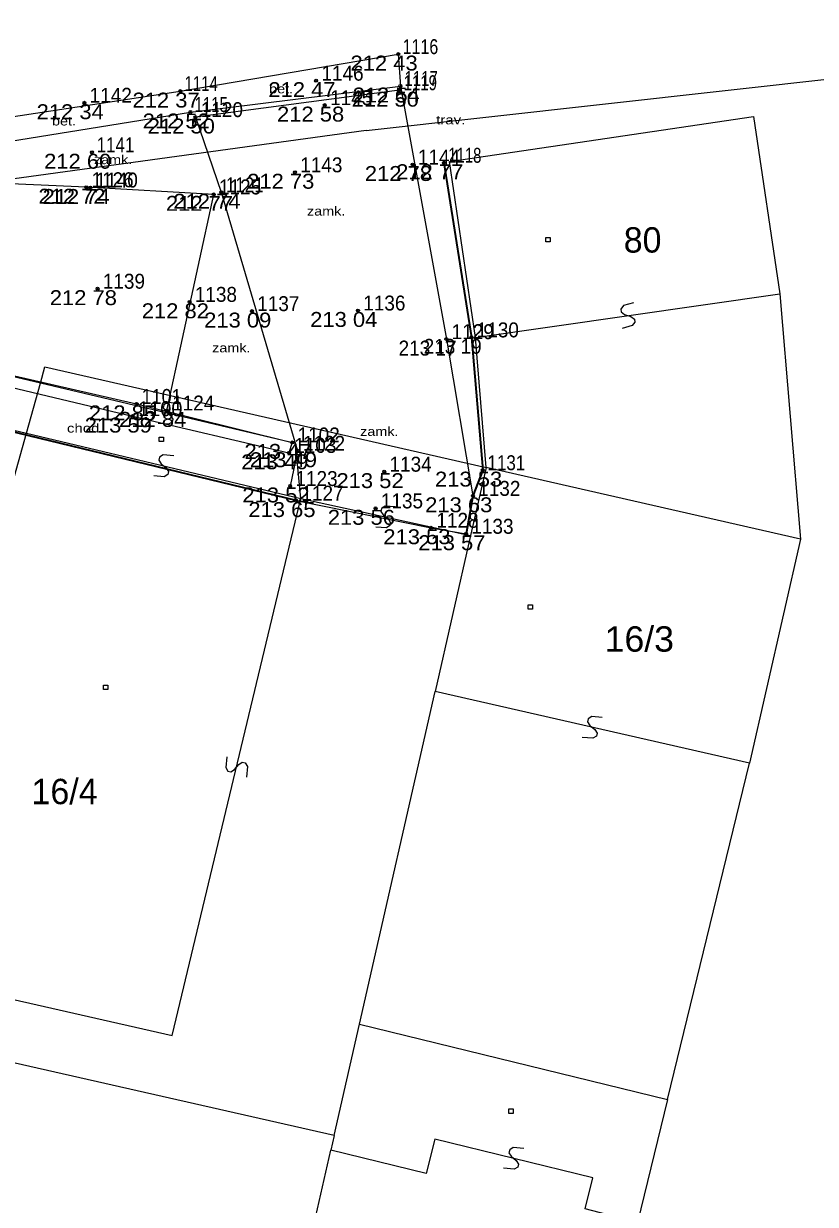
# Model space of a CAD drawing. Extents: x -736847 to -736508, y -1028413 to -1028271.
# Drawn here: x -736628.79 to -736602.28, y -1028331.58 to -1028292.02 of the extents above; entities that cross this region are included whole.
import ezdxf
from ezdxf.enums import TextEntityAlignment as Align

# ---------------------------------------------------------------- set-up
doc = ezdxf.new("R2010")
doc.units = 0
doc.header["$LTSCALE"] = 0.2
doc.header["$PDMODE"] = 32
doc.header["$PDSIZE"] = 0.1
for name, color, linetype, lineweight in [('1', 7, 'Continuous', 13), ('13', 7, 'Continuous', 13), ('14', 7, 'Continuous', 13), ('2', 7, 'Continuous', 13), ('6', 7, 'Continuous', 35), ('63', 7, 'Continuous', 13), ('8', 7, 'Continuous', 13)]:
    doc.layers.add(name, color=color, linetype=linetype, lineweight=lineweight)
for name, color, linetype in [('34', 7, 'Continuous'), ('35', 7, 'Continuous'), ('36', 7, 'Continuous'), ('60', 7, 'Continuous')]:
    doc.layers.add(name, color=color, linetype=linetype)

msp = doc.modelspace()

# ---------------------------------------------------------------- linework, layer by layer
at = {"layer": '1'}
for p, q in [((-736617.32, -1028295.6), (-736559.64, -1028289.16)), ((-736613.66, -1028302.53), (-736603.47, -1028301.07)), ((-736602.78, -1028309.29), (-736604.49, -1028316.8)), ((-736617.55, -1028325.54), (-736615.02, -1028314.4)), ((-736604.49, -1028316.8), (-736615.02, -1028314.4)), ((-736607.24, -1028328.06), (-736604.49, -1028316.8)), ((-736618.4, -1028329.27), (-736617.55, -1028325.54)), ((-736617.55, -1028325.54), (-736607.24, -1028328.06)), ((-736618.4, -1028329.27), (-736634.27, -1028325.67)), ((-736607.24, -1028328.06), (-736608.24, -1028332.18)), ((-736618.4, -1028329.27), (-736618.51, -1028329.76)), ((-736620.8, -1028339.79), (-736618.51, -1028329.76))]:
    msp.add_line(p, q, dxfattribs=at)
for points in [[(-736614.54, -1028296.64), (-736604.35, -1028295.13), (-736603.47, -1028301.07), (-736602.78, -1028309.29)], [(-736617.32, -1028295.6), (-736658.87, -1028301.31), (-736705.21, -1028307.67), (-736744.41, -1028313.05)], [(-736613.31, -1028306.89), (-736613.66, -1028302.53), (-736614.54, -1028296.64)], [(-736628.23, -1028304.07), (-736632.78, -1028302.99), (-736633.23, -1028304.71)], [(-736633.71, -1028323.67), (-736628.7, -1028305.74), (-736628.23, -1028304.07), (-736628.08, -1028303.52), (-736613.31, -1028306.89)], [(-736619.51, -1028307.93), (-736619.69, -1028306.09), (-736628.23, -1028304.07)], [(-736631.44, -1028305.09), (-736628.7, -1028305.74), (-736619.51, -1028307.93), (-736613.83, -1028309.17)], [(-736602.78, -1028309.29), (-736613.31, -1028306.89), (-736613.83, -1028309.17), (-736615.02, -1028314.4)], [(-736633.71, -1028323.67), (-736623.82, -1028325.92), (-736619.51, -1028307.93)], [(-736608.24, -1028332.18), (-736609.99, -1028331.73), (-736609.74, -1028330.69), (-736615.03, -1028329.39), (-736615.32, -1028330.54), (-736618.51, -1028329.76)]]:
    msp.add_lwpolyline(points, dxfattribs=at)
at = {"layer": '13'}
for points in [[(-736631.34, -1028295.46), (-736623.55, -1028294.28), (-736616.25, -1028293.04)], [(-736616.25, -1028293.04), (-736616.18, -1028294.11), (-736614.64, -1028302.59), (-736613.75, -1028307.84)], [(-736631.32, -1028296.29), (-736623.21, -1028294.98), (-736616.18, -1028294.11)]]:
    msp.add_lwpolyline(points, dxfattribs=at)
at = {"layer": '14'}
msp.add_lwpolyline([(-736624, -1028304.98), (-736622.43, -1028297.74), (-736626.7, -1028297.5), (-736631.5, -1028297.29)], dxfattribs=at)
at = {"layer": '2'}
for points in [[(-736611.31, -1028299.18), (-736611.16, -1028299.18), (-736611.16, -1028299.33), (-736611.31, -1028299.33)], [(-736624.26, -1028305.87), (-736624.11, -1028305.87), (-736624.11, -1028306.02), (-736624.26, -1028306.02)], [(-736611.9, -1028311.49), (-736611.75, -1028311.49), (-736611.75, -1028311.64), (-736611.9, -1028311.64)], [(-736626.12, -1028314.18), (-736625.97, -1028314.18), (-736625.97, -1028314.33), (-736626.12, -1028314.33)], [(-736612.55, -1028328.38), (-736612.4, -1028328.38), (-736612.4, -1028328.53), (-736612.55, -1028328.53)]]:
    msp.add_lwpolyline(points, close=True, dxfattribs=at)
for points in [[(-736608.374, -1028301.368), (-736608.713, -1028301.467), (-736608.798, -1028301.58), (-736608.784, -1028301.679), (-736608.671, -1028301.764), (-736608.458, -1028301.835), (-736608.345, -1028301.92), (-736608.331, -1028302.019), (-736608.416, -1028302.132), (-736608.755, -1028302.231)], [(-736623.624, -1028304.748), (-736623.976, -1028304.716), (-736624.097, -1028304.79), (-736624.12, -1028304.888), (-736624.045, -1028305.008), (-736623.874, -1028305.151), (-736623.799, -1028305.272), (-736623.822, -1028305.369), (-736623.943, -1028305.443), (-736624.295, -1028305.411)], [(-736623.769, -1028306.503), (-736624.121, -1028306.471), (-736624.241, -1028306.545), (-736624.264, -1028306.642), (-736624.19, -1028306.763), (-736624.019, -1028306.906), (-736623.945, -1028307.027), (-736623.968, -1028307.124), (-736624.088, -1028307.198), (-736624.44, -1028307.166)], [(-736616.34, -1028308.212), (-736616.693, -1028308.186), (-736616.812, -1028308.263), (-736616.833, -1028308.36), (-736616.757, -1028308.479), (-736616.582, -1028308.62), (-736616.506, -1028308.739), (-736616.527, -1028308.836), (-736616.646, -1028308.913), (-736616.999, -1028308.887)], [(-736609.422, -1028315.265), (-736609.774, -1028315.236), (-736609.894, -1028315.311), (-736609.916, -1028315.409), (-736609.841, -1028315.529), (-736609.668, -1028315.67), (-736609.593, -1028315.79), (-736609.615, -1028315.888), (-736609.735, -1028315.963), (-736610.087, -1028315.934)], [(-736621.995, -1028316.588), (-736622.028, -1028316.94), (-736621.954, -1028317.061), (-736621.857, -1028317.084), (-736621.736, -1028317.01), (-736621.593, -1028316.839), (-736621.472, -1028316.765), (-736621.375, -1028316.788), (-736621.301, -1028316.909), (-736621.334, -1028317.261)], [(-736612.046, -1028329.711), (-736612.398, -1028329.676), (-736612.519, -1028329.749), (-736612.543, -1028329.846), (-736612.47, -1028329.967), (-736612.299, -1028330.112), (-736612.226, -1028330.233), (-736612.25, -1028330.33), (-736612.371, -1028330.403), (-736612.723, -1028330.368)]]:
    msp.add_lwpolyline(points, dxfattribs=at)
at = {"layer": '34'}
for p in [(-736616.25, -1028293.04), (-736619, -1028293.93), (-736623.55, -1028294.28), (-736616.21, -1028294.25), (-736616.18, -1028294.11), (-736626.76, -1028294.67), (-736618.71, -1028294.75), (-736623.21, -1028294.98), (-736623.04, -1028295.15), (-736626.51, -1028296.33), (-736615.77, -1028296.74), (-736614.72, -1028296.68), (-736619.71, -1028297), (-736626.7, -1028297.5), (-736626.56, -1028297.51), (-736622.43, -1028297.74), (-736622.18, -1028297.67), (-736626.32, -1028300.9), (-736623.24, -1028301.34), (-736621.15, -1028301.65), (-736617.6, -1028301.63), (-736614.64, -1028302.59), (-736613.8, -1028302.53), (-736625.01, -1028304.76), (-736624, -1028304.98), (-736625.15, -1028305.17), (-736619.8, -1028306.05), (-736619.91, -1028306.4), (-736619.62, -1028306.33), (-736616.72, -1028307.03), (-736613.42, -1028306.98), (-736619.87, -1028307.51), (-736613.75, -1028307.84), (-736619.67, -1028308), (-736617.01, -1028308.26), (-736615.15, -1028308.91), (-736613.98, -1028309.11)]:
    msp.add_point(p, dxfattribs=at)
at = {"layer": '6'}
msp.add_line((-736619.67, -1028308), (-736631.58, -1028305.11), dxfattribs=at)
msp.add_lwpolyline([(-736614.72, -1028296.68), (-736613.8, -1028302.53), (-736613.42, -1028306.98), (-736613.75, -1028307.84), (-736613.98, -1028309.11)], dxfattribs=at)
at = {"layer": '63'}
msp.add_lwpolyline([(-736616.21, -1028294.25), (-736623.04, -1028295.15), (-736622.18, -1028297.67), (-736619.62, -1028306.33), (-736619.87, -1028307.51)], dxfattribs=at)
at = {"layer": '8'}
for points in [[(-736631.3, -1028303.32), (-736625.01, -1028304.76), (-736619.8, -1028306.05), (-736619.91, -1028306.4)], [(-736631.39, -1028303.69), (-736625.15, -1028305.17), (-736619.91, -1028306.4)], [(-736619.67, -1028308), (-736615.15, -1028308.91), (-736613.98, -1028309.11)]]:
    msp.add_lwpolyline(points, dxfattribs=at)

# ---------------------------------------------------------------- texts
at = {"layer": '2'}
for s, p in [('80', (-736608.7, -1028299.69)), ('16/4', (-736628.53, -1028318.17))]:
    msp.add_text(s, height=0.85, dxfattribs=at).set_placement(p)
at = {"layer": '2', "width": 1.05}
msp.add_text('16/3', height=0.85, dxfattribs=at).set_placement((-736609.34, -1028313.06))
at = {"layer": '35'}
for s, width, p in [(' 1116', 0.8, (-736616.25, -1028293.04)), (' 1146', 0.95, (-736619, -1028293.93)), (' 1114', 0.75, (-736623.55, -1028294.28)), (' 1119', 0.75, (-736616.21, -1028294.25)), (' 1117', 0.75, (-736616.18, -1028294.11)), (' 1142', 0.95, (-736626.76, -1028294.67)), (' 1145', 0.95, (-736618.71, -1028294.75)), (' 1115', 0.75, (-736623.21, -1028294.98)), (' 1120', 0.95, (-736623.04, -1028295.15)), (' 1141', 0.85, (-736626.51, -1028296.33)), (' 1144', 0.95, (-736615.77, -1028296.74)), (' 1118', 0.75, (-736614.72, -1028296.68)), (' 1143', 0.95, (-736619.71, -1028297)), (' 1126', 0.95, (-736626.7, -1028297.5)), (' 1140', 0.95, (-736626.56, -1028297.51)), (' 1121', 0.85, (-736622.18, -1028297.67)), (' 1125', 0.95, (-736622.43, -1028297.74)), (' 1139', 0.95, (-736626.32, -1028300.9)), (' 1138', 0.95, (-736623.24, -1028301.34)), (' 1137', 0.95, (-736621.15, -1028301.65)), (' 1136', 0.95, (-736617.6, -1028301.63)), (' 1129', 0.95, (-736614.64, -1028302.59)), (' 1130', 0.95, (-736613.8, -1028302.53)), (' 1101', 0.9, (-736625.01, -1028304.76)), (' 1124', 0.95, (-736624, -1028304.98)), (' 1102', 0.95, (-736619.8, -1028306.05)), (' 1122', 0.95, (-736619.62, -1028306.33)), (' 1103', 0.95, (-736619.91, -1028306.4)), (' 1134', 0.95, (-736616.72, -1028307.03)), (' 1131', 0.85, (-736613.42, -1028306.98)), (' 1123', 0.95, (-736619.87, -1028307.51)), (' 1132', 0.95, (-736613.75, -1028307.84)), (' 1127', 0.95, (-736619.67, -1028308)), (' 1135', 0.95, (-736617.01, -1028308.26)), (' 1128', 0.95, (-736615.15, -1028308.91)), (' 1133', 0.95, (-736613.98, -1028309.11))]:
    msp.add_text(s, height=0.5, dxfattribs=dict(at, width=width)).set_placement(p)
msp.add_text(' 1100', height=0.5, dxfattribs=at).set_placement((-736625.15, -1028305.17))
at = {"layer": '36'}
for s, width, p in [('212 43', 1.1, (-736617.85, -1028293.59)), ('212 47', 1.1, (-736620.6, -1028294.48)), ('212 37', 1.1, (-736625.15, -1028294.83)), ('212 50', 1.1, (-736617.81, -1028294.8)), ('212 54', 1.1, (-736617.78, -1028294.66)), ('212 34', 1.1, (-736628.36, -1028295.22)), ('212 52', 1.1, (-736624.81, -1028295.53)), ('212 58', 1.1, (-736620.31, -1028295.3)), ('212 50', 1.1, (-736624.64, -1028295.7)), ('212 60', 1.1, (-736628.11, -1028296.88)), ('212 77', 1.1, (-736616.32, -1028297.23)), ('212 73', 1.1, (-736621.31, -1028297.55)), ('212 78', 1.1, (-736617.37, -1028297.29)), ('212 72', 1.1, (-736628.3, -1028298.05)), ('212 74', 1.1, (-736628.16, -1028298.06)), ('212 77', 1.1, (-736624.03, -1028298.29)), ('212 74', 1.1, (-736623.78, -1028298.22)), ('212 78', 1.1, (-736627.92, -1028301.45)), ('212 82', 1.1, (-736624.84, -1028301.89)), ('213 09', 1.1, (-736622.75, -1028302.2)), ('213 04', 1.1, (-736619.2, -1028302.18)), ('213 17', 0.95, (-736616.24, -1028303.14)), ('213 19', 0.95, (-736615.4, -1028303.08)), ('212 85', 1.1, (-736626.61, -1028305.31)), ('212 84', 1.1, (-736625.6, -1028305.53)), ('213 59', 1.1, (-736626.75, -1028305.72)), ('213 47', 1.1, (-736621.4, -1028306.6)), ('213 49', 1.1, (-736621.51, -1028306.95)), ('213 49', 1.1, (-736621.22, -1028306.88)), ('213 53', 1.1, (-736615.02, -1028307.53)), ('213 52', 1.1, (-736618.32, -1028307.58)), ('213 52', 1.1, (-736621.47, -1028308.06)), ('213 65', 1.1, (-736621.27, -1028308.55)), ('213 63', 1.1, (-736615.35, -1028308.39)), ('213 56', 1.1, (-736618.61, -1028308.81)), ('213 53', 1.1, (-736616.75, -1028309.46)), ('213 57', 1.1, (-736615.58, -1028309.66))]:
    msp.add_text(s, height=0.5, dxfattribs=dict(at, width=width)).set_placement(p)
at = {"layer": '60'}
for s, width, p in [('bet.', 1.2, (-736620.172, -1028294.353)), ('bet.', 1.2, (-736627.443, -1028295.431)), ('trav.', 1.25, (-736614.493, -1028295.392)), ('zamk.', 1.2, (-736625.799, -1028296.726)), ('zamk.', 1.2, (-736618.664, -1028298.449)), ('zamk.', 1.2, (-736621.841, -1028303.03)), ('chod.', 1.25, (-736626.73, -1028305.722)), ('zamk.', 1.2, (-736616.885, -1028305.832))]:
    msp.add_text(s, height=0.3, dxfattribs=dict(at, width=width)).set_placement(p, align=Align.CENTER)

doc.saveas('drawing.dxf')
